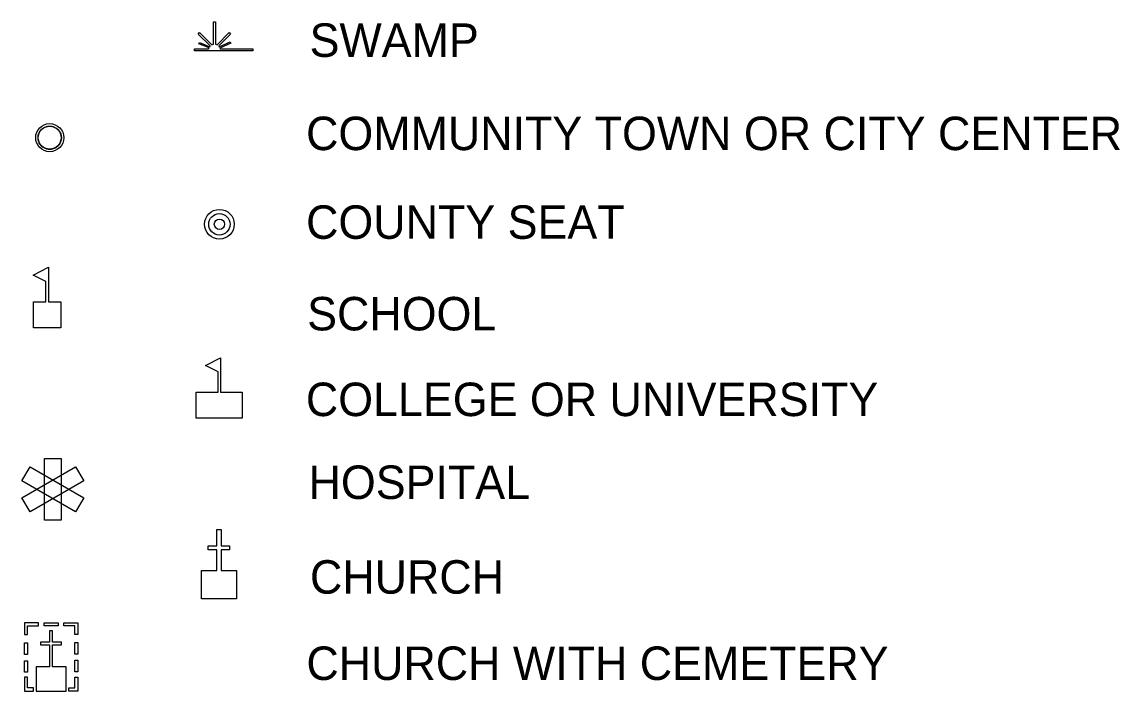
# Model space of a CAD drawing. Extents: x 5197761 to 5514561, y 1890130 to 2080942.
# Drawn here: x 5487546 to 5503940, y 1985722 to 1995717 of the extents above; entities that cross this region are included whole.
import ezdxf

# ---------------------------------------------------------------- set-up
doc = ezdxf.new("R2010")
doc.units = 0
for name, color, linetype in [('Exist Civil Demographics Community CELL', 7, 'Continuous'), ('Exist Civil Demographics Community Label', 7, 'Continuous'), ('Exist Civil Demographics County Seat CELL', 7, 'Continuous'), ('Exist Civil Demographics County Seat Label', 7, 'Continuous'), ('Exist Cultural Church CELL', 7, 'Continuous'), ('Exist Cultural Church Label', 7, 'Continuous'), ('Exist Cultural Church with Cemetary CELL', 7, 'Continuous'), ('Exist Cultural Church with Cemetary Label', 7, 'Continuous'), ('Exist Cultural Educational Facility College or University CELL', 7, 'Continuous'), ('Exist Cultural Educational Facility College or University Label', 7, 'Continuous'), ('Exist Cultural Educational Facility High CELL', 7, 'Continuous'), ('Exist Cultural Educational Facility High Label', 7, 'Continuous'), ('Exist Cultural Hospital CELL', 7, 'Continuous'), ('Exist Cultural Hospital Label', 7, 'Continuous'), ('Exist Hydrographic Swamp CELL', 7, 'Continuous'), ('Exist Hydrographic Swamp Label', 7, 'Continuous')]:
    doc.layers.add(name, color=color, linetype=linetype)

msp = doc.modelspace()

# ---------------------------------------------------------------- linework, layer by layer
at = {"layer": 'Exist Civil Demographics Community CELL'}
msp.add_lwpolyline([(5487788, 1994015), (5487790, 1994028), (5487794, 1994042), (5487801, 1994058), (5487807, 1994071), (5487815, 1994084), (5487823, 1994095), (5487832, 1994105), (5487842, 1994115), (5487854, 1994125), (5487867, 1994133), (5487877, 1994140), (5487889, 1994145), (5487901, 1994150), (5487913, 1994154), (5487923, 1994157), (5487934, 1994158), (5487943, 1994160), (5487957, 1994161), (5487967, 1994160), (5487979, 1994160), (5487990, 1994158), (5488001, 1994156), (5488012, 1994153), (5488024, 1994149), (5488039, 1994142), (5488053, 1994134), (5488064, 1994126), (5488075, 1994118), (5488083, 1994111), (5488092, 1994101), (5488100, 1994090), (5488107, 1994080), (5488114, 1994069), (5488120, 1994058), (5488124, 1994046), (5488128, 1994035), (5488130, 1994025), (5488133, 1994012), (5488134, 1994001), (5488135, 1993988), (5488134, 1993975), (5488133, 1993962), (5488131, 1993950), (5488127, 1993937), (5488123, 1993924), (5488118, 1993912), (5488111, 1993899), (5488104, 1993887), (5488096, 1993877), (5488087, 1993866), (5488075, 1993855), (5488064, 1993846), (5488053, 1993838), (5488043, 1993833), (5488028, 1993826), (5488012, 1993820), (5487999, 1993816), (5487984, 1993813), (5487974, 1993812), (5487964, 1993812), (5487952, 1993812), (5487942, 1993813), (5487930, 1993814), (5487917, 1993817), (5487907, 1993820), (5487895, 1993824), (5487885, 1993829), (5487876, 1993834), (5487861, 1993843), (5487849, 1993852), (5487838, 1993862), (5487828, 1993873), (5487821, 1993882), (5487814, 1993891), (5487805, 1993907), (5487801, 1993915), (5487797, 1993924), (5487792, 1993942), (5487788, 1993957), (5487787, 1993969), (5487786, 1993983), (5487786, 1993993), (5487787, 1994008)], close=True, dxfattribs=at)
for centre, radius in [((5487961, 1993988), 210), ((5487960, 1993988), 170)]:
    msp.add_circle(centre, radius, dxfattribs=at)
at = {"layer": 'Exist Civil Demographics County Seat CELL'}
for radius in [222, 160, 77]:
    msp.add_circle((5490494, 1992694), radius, dxfattribs=at)
at = {"layer": 'Exist Cultural Church CELL'}
msp.add_lwpolyline([(5490226, 1987524), (5490454, 1987525), (5490454, 1987829), (5490326, 1987829), (5490326, 1987893), (5490454, 1987893), (5490454, 1988134), (5490518, 1988134), (5490518, 1987893), (5490646, 1987893), (5490646, 1987829), (5490518, 1987829), (5490518, 1987525), (5490748, 1987524), (5490748, 1987098), (5490226, 1987098)], close=True, dxfattribs=at)
at = {"layer": 'Exist Cultural Church with Cemetary CELL'}
for points in [[(5487584, 1986567), (5487629, 1986567), (5487629, 1986696), (5487791, 1986696), (5487791, 1986740), (5487584, 1986740)], [(5487756, 1985722), (5488205, 1985722), (5488205, 1986084), (5488002, 1986084), (5488002, 1986410), (5488134, 1986410), (5488134, 1986454), (5488002, 1986454), (5488002, 1986623), (5487955, 1986623), (5487955, 1986454), (5487823, 1986454), (5487823, 1986410), (5487955, 1986410), (5487955, 1986084), (5487756, 1986084)], [(5487880, 1986740), (5488087, 1986740), (5488087, 1986695), (5487880, 1986695)], [(5488380, 1986567), (5488335, 1986567), (5488335, 1986696), (5488173, 1986696), (5488173, 1986740), (5488380, 1986740)], [(5487584, 1986270), (5487584, 1986444), (5487629, 1986444), (5487629, 1986270)], [(5488335, 1986275), (5488335, 1986448), (5488380, 1986448), (5488380, 1986275)], [(5487584, 1986002), (5487584, 1986175), (5487629, 1986175), (5487629, 1986002)], [(5488335, 1986011), (5488335, 1986184), (5488380, 1986184), (5488380, 1986011)], [(5487716, 1985722), (5487716, 1985768), (5487628, 1985768), (5487628, 1985930), (5487583, 1985930), (5487583, 1985722)], [(5488248, 1985722), (5488248, 1985768), (5488335, 1985768), (5488335, 1985929), (5488380, 1985929), (5488380, 1985722)]]:
    msp.add_lwpolyline(points, close=True, dxfattribs=at)
at = {"layer": 'Exist Cultural Educational Facility College or University CELL'}
msp.add_lwpolyline([(5490149, 1989796), (5490149, 1990187), (5490473, 1990187), (5490473, 1990488), (5490285, 1990585), (5490511, 1990701), (5490511, 1990187), (5490835, 1990187), (5490835, 1989796)], close=True, dxfattribs=at)
at = {"layer": 'Exist Cultural Educational Facility High CELL'}
msp.add_lwpolyline([(5487718, 1991146), (5487718, 1991538), (5487902, 1991538), (5487902, 1991838), (5487714, 1991935), (5487940, 1992052), (5487940, 1991538), (5488125, 1991538), (5488125, 1991146)], close=True, dxfattribs=at)
at = {"layer": 'Exist Cultural Hospital CELL'}
for points in [[(5487668, 1988399), (5487546, 1988610), (5488346, 1989072), (5488468, 1988861)], [(5488468, 1988610), (5488346, 1988399), (5487546, 1988861), (5487668, 1989072)], [(5488129, 1988274), (5487885, 1988274), (5487885, 1989198), (5488129, 1989198)]]:
    msp.add_lwpolyline(points, close=True, dxfattribs=at)
at = {"layer": 'Exist Hydrographic Swamp CELL'}
msp.add_lwpolyline([(5490121, 1995315), (5490331, 1995315), (5490339, 1995329), (5490186, 1995389), (5490198, 1995410), (5490349, 1995347), (5490355, 1995358), (5490178, 1995536), (5490198, 1995557), (5490379, 1995375), (5490405, 1995384), (5490405, 1995717), (5490434, 1995717), (5490433, 1995384), (5490459, 1995375), (5490640, 1995557), (5490661, 1995536), (5490483, 1995358), (5490491, 1995344), (5490654, 1995418), (5490664, 1995398), (5490500, 1995327), (5490507, 1995315), (5490991, 1995315), (5490991, 1995286), (5490121, 1995286)], close=True, dxfattribs=at)

# ---------------------------------------------------------------- texts
at = {"layer": 'Exist Civil Demographics Community Label'}
msp.add_text('COMMUNITY TOWN OR CITY CENTER', height=500, dxfattribs=at).set_placement((5491788, 1993802))
at = {"layer": 'Exist Civil Demographics County Seat Label'}
msp.add_text('COUNTY SEAT', height=500, dxfattribs=at).set_placement((5491788, 1992477))
at = {"layer": 'Exist Cultural Church Label'}
msp.add_text('CHURCH', height=500, dxfattribs=at).set_placement((5491846, 1987176))
at = {"layer": 'Exist Cultural Church with Cemetary Label'}
msp.add_text('CHURCH WITH CEMETERY', height=500, dxfattribs=at).set_placement((5491793, 1985887))
at = {"layer": 'Exist Cultural Educational Facility College or University Label'}
msp.add_text('COLLEGE OR UNIVERSITY', height=500, dxfattribs=at).set_placement((5491785, 1989829))
at = {"layer": 'Exist Cultural Educational Facility High Label'}
msp.add_text('SCHOOL', height=500, dxfattribs=at).set_placement((5491804, 1991109))
at = {"layer": 'Exist Cultural Hospital Label'}
msp.add_text('HOSPITAL', height=500, dxfattribs=at).set_placement((5491825, 1988591))
at = {"layer": 'Exist Hydrographic Swamp Label'}
msp.add_text('SWAMP', height=500, dxfattribs=at).set_placement((5491840, 1995195))

doc.saveas('drawing.dxf')
